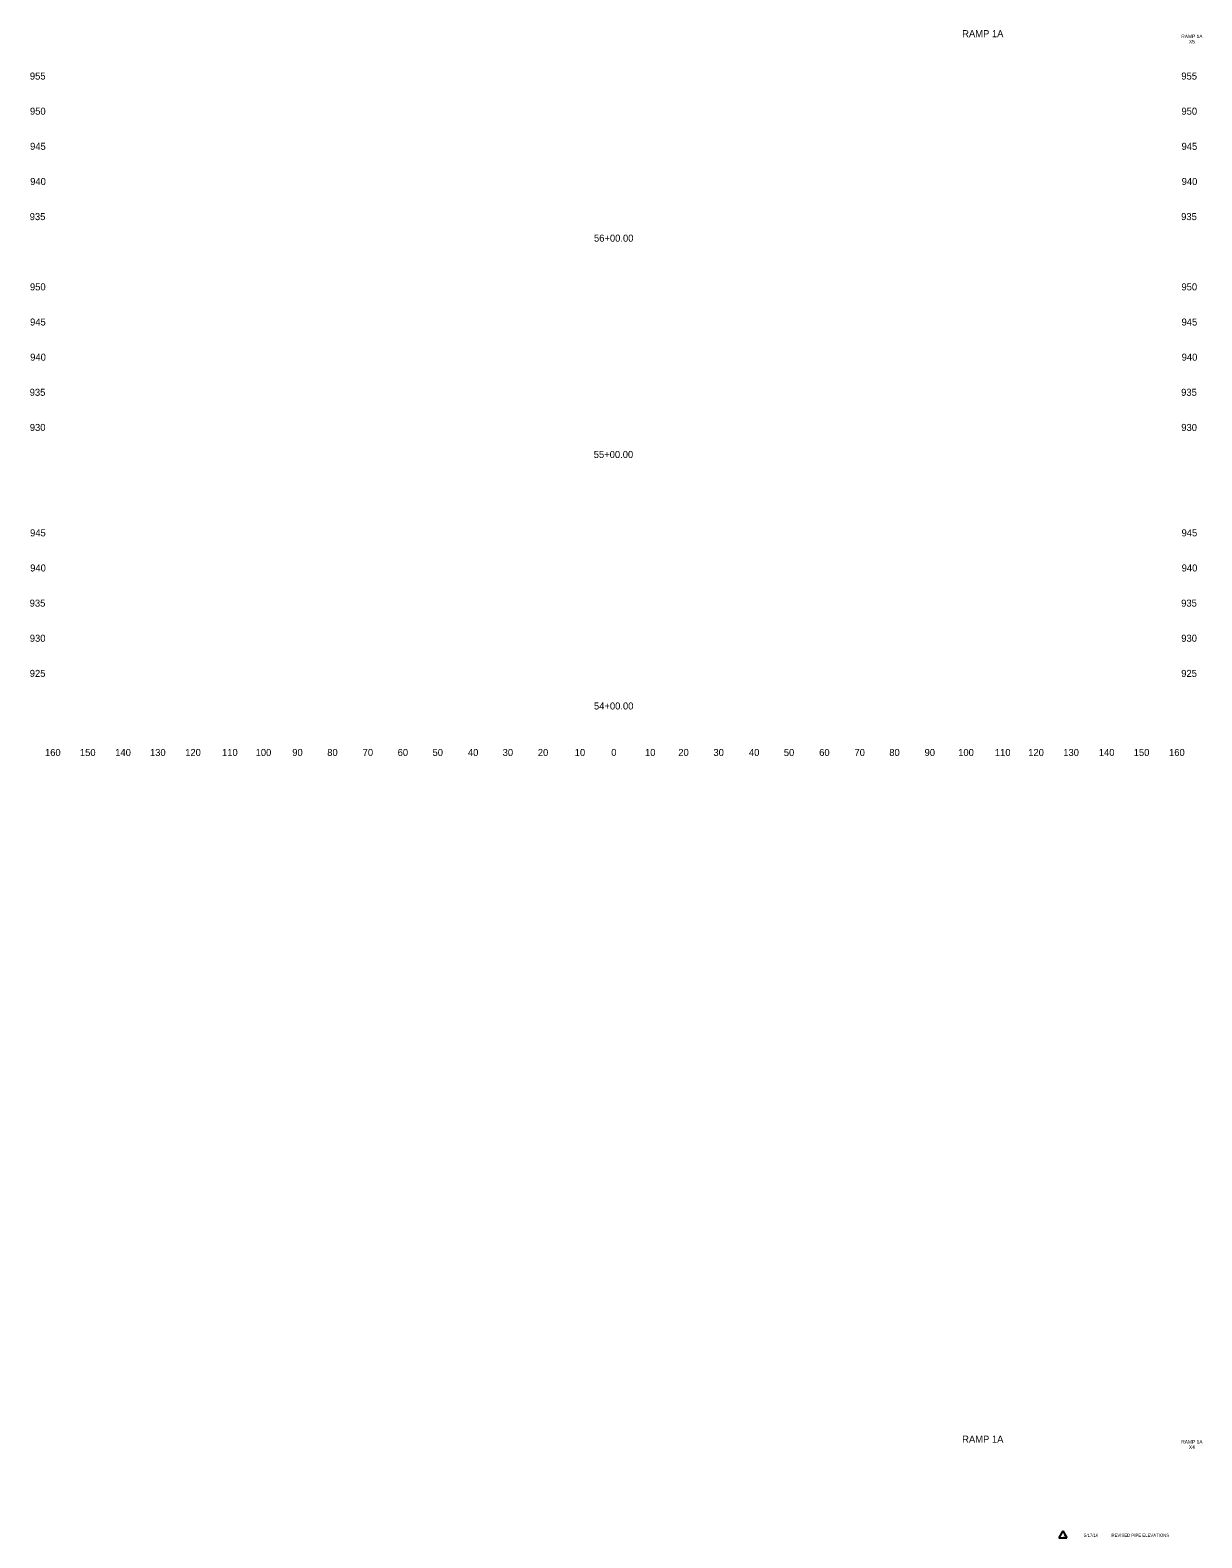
# Model space of a CAD drawing. Extents: x 4994 to 6873, y 4997 to 8804.
# Drawn here: x 4993.9 to 5327.4, y 6375 to 6804.1 of the extents above; entities that cross this region are included whole.
import ezdxf

# ---------------------------------------------------------------- set-up
doc = ezdxf.new("R2010")
doc.units = 0
for name, color, linetype in [('RD_SHT_ID', 7, 'Continuous'), ('RD_SHT_TX', 7, 'Continuous'), ('RD_XS_TX_Offset', 7, 'Continuous'), ('RD_XS_TX_Station', 7, 'Continuous')]:
    doc.layers.add(name, color=color, linetype=linetype)

msp = doc.modelspace()

# ---------------------------------------------------------------- linework, layer by layer
at = {"layer": 'RD_SHT_TX'}
for p, q in [((5287.89, 6377.01), (5286.75, 6374.98)), ((5287.89, 6377.01), (5289.03, 6374.98)), ((5286.75, 6374.98), (5289.03, 6374.98))]:
    msp.add_line(p, q, dxfattribs=at)

# ---------------------------------------------------------------- texts
at = {"layer": 'RD_SHT_ID'}
for s, height, p in [('RAMP 1A', 2, (5259.21, 6802.06)), ('RAMP 1A', 1, (5321.57, 6801.8)), ('X5', 1, (5323.74, 6800.3)), ('RAMP 1A', 2, (5259.21, 6402.06)), ('RAMP 1A', 1, (5321.57, 6401.8)), ('X4', 1, (5323.74, 6400.3))]:
    msp.add_text(s, height=height, dxfattribs=at).set_placement(p)
at = {"layer": 'RD_SHT_TX'}
for s, p in [('1', (5287.89, 6375.31)), ('5/17/16', (5293.88, 6375.27)), ('REVISED PIPE ELEVATIONS', (5301.71, 6375.27))]:
    msp.add_text(s, height=0.88, dxfattribs=at).set_placement(p)
at = {"layer": 'RD_XS_TX_Offset'}
for s, p in [('955', (4993.8, 6790)), ('955', (5321.6, 6790)), ('950', (4993.83, 6780)), ('950', (5321.63, 6780)), ('945', (4993.86, 6770)), ('945', (5321.66, 6770)), ('940', (4993.89, 6760)), ('940', (5321.69, 6760)), ('935', (4993.75, 6750)), ('935', (5321.55, 6750)), ('950', (4993.83, 6730)), ('950', (5321.63, 6730)), ('945', (4993.86, 6720)), ('945', (5321.66, 6720)), ('940', (4993.89, 6710)), ('940', (5321.69, 6710)), ('935', (4993.75, 6700)), ('935', (5321.55, 6700)), ('930', (4993.78, 6690)), ('930', (5321.58, 6690)), ('945', (4993.86, 6660)), ('945', (5321.66, 6660)), ('940', (4993.89, 6650)), ('940', (5321.69, 6650)), ('935', (4993.75, 6640)), ('935', (5321.55, 6640)), ('930', (4993.78, 6630)), ('930', (5321.58, 6630)), ('925', (4993.77, 6620)), ('925', (5321.57, 6620)), ('160', (4998.1, 6597.5)), ('150', (5008.04, 6597.5)), ('140', (5018.1, 6597.5)), ('130', (5027.99, 6597.5)), ('120', (5038.01, 6597.5)), ('110', (5048.51, 6597.5)), ('100', (5058.07, 6597.5)), ('90', (5068.5, 6597.5)), ('80', (5078.46, 6597.5)), ('70', (5088.54, 6597.5)), ('60', (5098.5, 6597.5)), ('50', (5108.43, 6597.5)), ('40', (5118.5, 6597.5)), ('30', (5128.39, 6597.5)), ('20', (5138.4, 6597.5)), ('10', (5148.91, 6597.5)), ('0', (5159.3, 6597.5)), ('0', (5159.3, 6597.5)), ('10', (5168.91, 6597.5)), ('20', (5178.4, 6597.5)), ('30', (5188.39, 6597.5)), ('40', (5198.5, 6597.5)), ('50', (5208.43, 6597.5)), ('60', (5218.5, 6597.5)), ('70', (5228.54, 6597.5)), ('80', (5238.46, 6597.5)), ('90', (5248.5, 6597.5)), ('100', (5258.07, 6597.5)), ('110', (5268.51, 6597.5)), ('120', (5278.01, 6597.5)), ('130', (5287.99, 6597.5)), ('140', (5298.1, 6597.5)), ('150', (5308.04, 6597.5)), ('160', (5318.1, 6597.5))]:
    msp.add_text(s, height=2, dxfattribs=at).set_placement(p)
at = {"layer": 'RD_XS_TX_Station'}
for s, p in [('56+00.00', (5154.39, 6743.87)), ('55+00.00', (5154.32, 6682.3)), ('54+00.00', (5154.39, 6610.73))]:
    msp.add_text(s, height=2, dxfattribs=at).set_placement(p)

doc.saveas('drawing.dxf')
